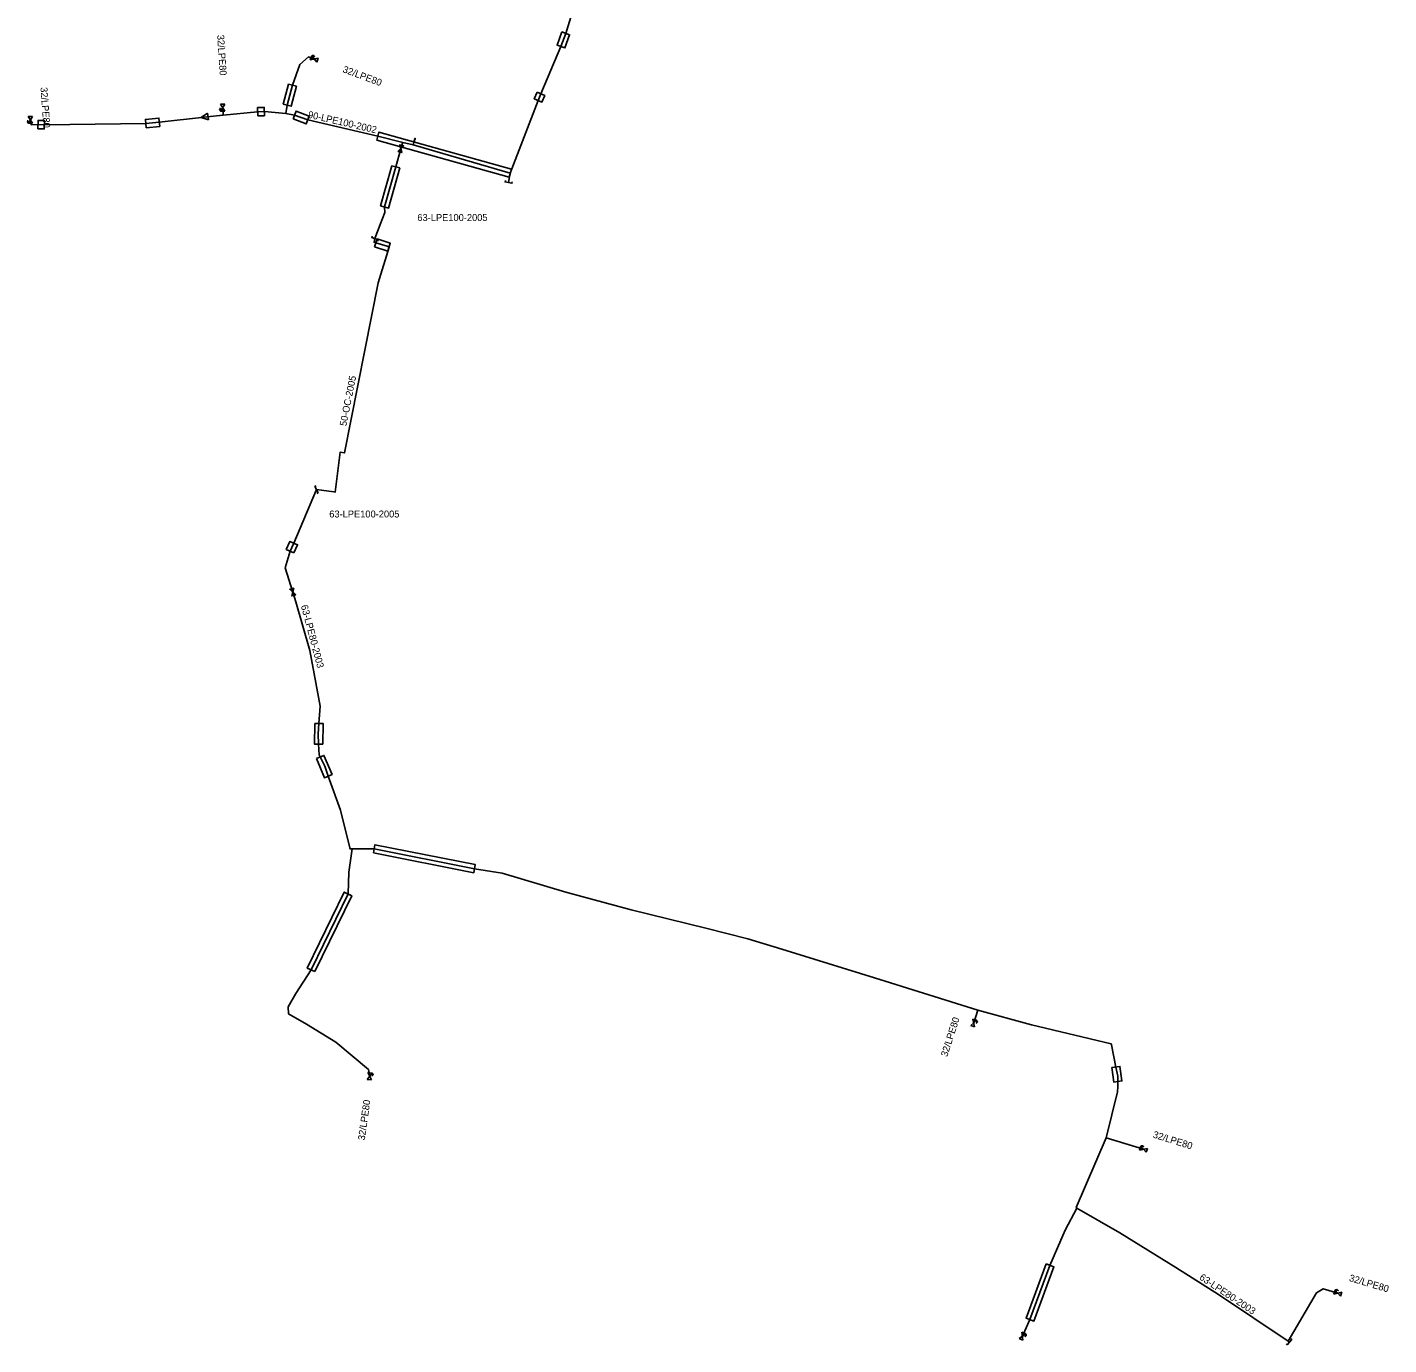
# Model space of a CAD drawing. Extents: x -787723 to -786204, y -1153846 to -1152384.
# Drawn here: x -787467.5 to -787271.2, y -1153161.4 to -1152971.6 of the extents above; entities that cross this region are included whole.
import ezdxf

# ---------------------------------------------------------------- set-up
doc = ezdxf.new("R2010")
doc.units = 0
for name, color, linetype in [('Vrstva 1', 7, 'Continuous'), ('Vrstva 21', 7, 'Continuous'), ('Vrstva 22', 7, 'Continuous'), ('Vrstva 25', 7, 'Continuous'), ('Vrstva 26', 7, 'Continuous'), ('Vrstva 28', 7, 'Continuous'), ('Vrstva 29', 7, 'Continuous'), ('Vrstva 31', 7, 'Continuous'), ('Vrstva 32', 7, 'Continuous')]:
    doc.layers.add(name, color=color, linetype=linetype)

# ---------------------------------------------------------------- blocks, each defined once
blk = doc.blocks.new('DEC123')
at = {"layer": 'Vrstva 1'}
blk.add_lwpolyline([(0.2, 0.5), (0, 0.5), (0, -0.5), (-0.2, -0.5)], dxfattribs=at)
blk = doc.blocks.new('DEC122')
at = {"layer": 'Vrstva 1'}
for p, q in [((-0.5, 0.5), (0.5, 0)), ((-0.5, -0.5), (-0.5, 0.5)), ((0.5, 0), (-0.5, -0.5))]:
    blk.add_line(p, q, dxfattribs=at)
blk = doc.blocks.new('DEC063-SN')
at = {"layer": 'Vrstva 1'}
for p, q in [((-0.5, -0.3), (0.5, 0.3)), ((0.5, -0.3), (-0.5, 0.3)), ((-0.5, 0.3), (-0.5, -0.3)), ((0.5, 0.3), (0.5, -0.3)), ((0.126, -0.318), (0.126, -0.458)), ((0.126, -0.384), (0.206, -0.384)), ((0.206, -0.458), (0.206, -0.318)), ((0.366, -0.458), (0.366, -0.318))]:
    blk.add_line(p, q, dxfattribs=at)
for points in [[(0.246, -0.318), (0.246, -0.418), (0.252, -0.438), (0.264, -0.451), (0.281, -0.458), (0.292, -0.458), (0.309, -0.451), (0.321, -0.438), (0.326, -0.418), (0.326, -0.318)], [(0.366, -0.318), (0.418, -0.318), (0.435, -0.325), (0.441, -0.331), (0.446, -0.344), (0.446, -0.364), (0.441, -0.378), (0.435, -0.384), (0.418, -0.391), (0.366, -0.391)]]:
    blk.add_lwpolyline(points, dxfattribs=at)
blk = doc.blocks.new('DEC130')
at = {"layer": 'Vrstva 1'}
blk.add_lwpolyline([(0.2, 0.5), (0, 0.5), (0, -0.5), (0.2, -0.5)], dxfattribs=at)
blk = doc.blocks.new('DEC124')
at = {"layer": 'Vrstva 1'}
blk.add_lwpolyline([(-0.5, 0.3), (0.5, -0.3), (0.5, 0.3), (-0.5, -0.3), (-0.5, 0.3)], dxfattribs=at)
blk = doc.blocks.new('DEC127')
at = {"layer": 'Vrstva 1'}
for p, q in [((0, 0.56), (0, 0.99)), ((0, 0.42), (0, -0.01))]:
    blk.add_line(p, q, dxfattribs=at)
blk.add_lwpolyline([(-0.07, 0.82), (0, 0.99), (0.07, 0.82)], dxfattribs=at)
blk.add_circle((0, 0.49), 0.07, dxfattribs=at)

msp = doc.modelspace()

# ---------------------------------------------------------------- linework, layer by layer
at = {"layer": 'Vrstva 21'}
for points in [[(-787334.68, -1152764.41), (-787335.37, -1152773.31), (-787335.76, -1152787.99), (-787335.85, -1152796.93), (-787336.15, -1152812.79), (-787336.74, -1152825.56), (-787338.63, -1152836.89), (-787341.8, -1152849.26), (-787345.88, -1152859.17), (-787354.3, -1152875.54), (-787363.3, -1152892.46), (-787369.92, -1152905.89), (-787373.75, -1152916.59), (-787378.4, -1152930.29), (-787381.12, -1152940.81), (-787381.21, -1152941.76), (-787383.36, -1152950.95), (-787386.31, -1152960.92), (-787389.85, -1152972.44), (-787390.54, -1152974.33), (-787393.42, -1152981.16), (-787393.84, -1152982.11), (-787397.85, -1152992.58)], [(-787413.33, -1152988.15), (-787416.93, -1152987.25), (-787427.03, -1152984.92), (-787428.92, -1152984.21), (-787430.18, -1152984.01), (-787433.28, -1152983.72), (-787434.25, -1152983.74), (-787439.24, -1152984.24), (-787441.56, -1152984.45), (-787441.9, -1152984.5)], [(-787413.33, -1152988.15), (-787413.51, -1152988.66), (-787413.62, -1152989.06)], [(-787397.85, -1152992.58), (-787411.83, -1152988.52), (-787413.33, -1152988.15)], [(-787413.62, -1152989.06), (-787414.35, -1152991.67), (-787415.96, -1152997.45), (-787415.94, -1152998.26)], [(-787397.85, -1152992.58), (-787398.1, -1152993.95)], [(-787415.94, -1152998.26), (-787416.59, -1153000), (-787417.34, -1153002.02)], [(-787417.34, -1153002.02), (-787417.48, -1153002.53), (-787417.21, -1153002.64), (-787415.57, -1153003.11), (-787415.32, -1153003.25), (-787416.86, -1153008.38), (-787421.72, -1153032.9), (-787422.38, -1153032.81), (-787423.06, -1153038.53), (-787423.27, -1153038.5), (-787425.77, -1153038.19)], [(-787430.26, -1153049.44), (-787429.57, -1153047.05), (-787429.34, -1153046.53), (-787429.05, -1153045.89), (-787425.77, -1153038.19)], [(-787430.26, -1153049.44), (-787429.19, -1153052.94)], [(-787429.19, -1153052.94), (-787428.77, -1153054.34), (-787426.73, -1153061.36), (-787425.26, -1153069.4), (-787425.43, -1153071.87), (-787425.53, -1153073.37), (-787425.46, -1153074.86), (-787425.39, -1153076.42), (-787425.24, -1153076.71), (-787424.57, -1153078.05), (-787424.07, -1153079.46), (-787422.33, -1153084.37), (-787420.96, -1153089.78)], [(-787420.96, -1153089.78), (-787420.92, -1153089.96), (-787420.62, -1153089.96), (-787417.46, -1153089.95), (-787402.99, -1153092.81), (-787399.02, -1153093.46), (-787389.85, -1153096.19), (-787380.41, -1153098.73), (-787369.68, -1153101.37), (-787363.63, -1153102.9), (-787358.73, -1153104.42), (-787345.38, -1153108.54), (-787330.47, -1153113.21), (-787322.74, -1153115.32), (-787311.24, -1153118.07), (-787311.22, -1153118.17)], [(-787311.22, -1153118.17), (-787310.58, -1153121.4), (-787310.31, -1153122.72), (-787310.29, -1153123.48), (-787310.27, -1153124.18), (-787310.36, -1153124.94), (-787311.95, -1153131.57), (-787316.28, -1153141.64), (-787316.2, -1153141.75), (-787310, -1153145.29), (-787301.94, -1153150.29), (-787295.79, -1153154.17), (-787285.74, -1153160.87), (-787285.56, -1153161.04)]]:
    msp.add_lwpolyline(points, dxfattribs=at)
at = {"layer": 'Vrstva 29'}
for points in [[(-787390.41, -1152972.23), (-787389.29, -1152972.65), (-787389.98, -1152974.53), (-787391.1, -1152974.12)], [(-787429.81, -1152979.76), (-787428.65, -1152980.06), (-787429.4, -1152982.94), (-787430.56, -1152982.64)], [(-787393.97, -1152980.92), (-787392.87, -1152981.4), (-787393.29, -1152982.35), (-787394.39, -1152981.87)], [(-787450.31, -1152986.03), (-787450.43, -1152984.83), (-787448.48, -1152984.64), (-787448.36, -1152985.84)], [(-787434.24, -1152984.34), (-787434.26, -1152983.14), (-787433.29, -1152983.12), (-787433.27, -1152984.32)], [(-787429.13, -1152984.77), (-787428.71, -1152983.65), (-787426.82, -1152984.36), (-787427.24, -1152985.48)], [(-787465.94, -1152986.18), (-787465.88, -1152984.98), (-787464.95, -1152985.02), (-787465.01, -1152986.22)], [(-787417.09, -1152987.83), (-787416.77, -1152986.67), (-787397.69, -1152992), (-787398.01, -1152993.16)], [(-787414.93, -1152991.51), (-787413.77, -1152991.83), (-787415.39, -1152997.61), (-787416.54, -1152997.29)], [(-787417.39, -1153003.21), (-787417.03, -1153002.07), (-787415.14, -1153002.68), (-787415.5, -1153003.82)], [(-787429.02, -1153047.29), (-787430.12, -1153046.8), (-787429.6, -1153045.64), (-787428.5, -1153046.14)], [(-787426.03, -1153071.87), (-787424.83, -1153071.88), (-787424.86, -1153074.86), (-787426.06, -1153074.85)], [(-787425.79, -1153076.95), (-787424.69, -1153076.48), (-787423.52, -1153079.23), (-787424.62, -1153079.7)], [(-787417.57, -1153090.54), (-787417.34, -1153089.36), (-787402.88, -1153092.22), (-787403.11, -1153093.4)], [(-787426.02, -1153107.64), (-787427.1, -1153107.12), (-787421.76, -1153096.19), (-787420.68, -1153096.71)], [(-787311.17, -1153121.48), (-787309.98, -1153121.31), (-787309.7, -1153123.4), (-787310.89, -1153123.56)], [(-787320.63, -1153149.77), (-787319.5, -1153150.18), (-787322.39, -1153157.99), (-787323.52, -1153157.57)]]:
    msp.add_lwpolyline(points, close=True, dxfattribs=at)
at = {"layer": 'Vrstva 31'}
for points in [[(-787430.18, -1152984.01), (-787429.98, -1152982.79), (-787429.23, -1152979.91), (-787428.18, -1152976.94), (-787426.92, -1152975.83), (-787426.09, -1152976.14)], [(-787441.9, -1152984.5), (-787448.42, -1152985.24), (-787450.37, -1152985.43), (-787464.98, -1152985.62), (-787465.91, -1152985.58), (-787466.9, -1152985.6), (-787466.99, -1152984.9)], [(-787439.24, -1152984.24), (-787439.28, -1152983.15)], [(-787420.62, -1153089.96), (-787421.1, -1153093.3), (-787421.22, -1153096.45), (-787426.56, -1153107.38), (-787428.77, -1153110.77), (-787429.87, -1153112.71), (-787429.78, -1153113.74), (-787427.19, -1153115.21), (-787423, -1153117.82), (-787418.26, -1153121.76), (-787418.1, -1153122.72)], [(-787330.47, -1153113.21), (-787331.06, -1153115.04)], [(-787311.95, -1153131.57), (-787306.6, -1153133.24)], [(-787316.2, -1153141.75), (-787317.88, -1153144.92), (-787320.07, -1153149.97), (-787322.96, -1153157.78), (-787324.04, -1153160.16)], [(-787285.74, -1153160.87), (-787281.64, -1153153.94), (-787280.7, -1153153.34), (-787278.58, -1153153.97)]]:
    msp.add_lwpolyline(points, dxfattribs=at)

# ---------------------------------------------------------------- block references
at = {"layer": 'Vrstva 22'}
for name, p, rotation in [('DEC124', (-787413.62, -1152989.06), 74.49066386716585), ('DEC130', (-787398.1, -1152993.95), 78.80488889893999), ('DEC124', (-787429.19, -1153052.94), -72.98588883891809), ('DEC130', (-787285.56, -1153161.04), 137.26475556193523)]:
    msp.add_blockref(name, p, dxfattribs=dict(at, rotation=rotation))
at = {"layer": 'Vrstva 25'}
for p, rotation in [((-787417.34, -1153002.02), 69.57766670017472), ((-787425.77, -1153038.19), 28.653794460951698)]:
    msp.add_blockref('DEC123', p, dxfattribs=dict(at, rotation=rotation))
at = {"layer": 'Vrstva 26', "rotation": -171.63411382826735}
msp.add_blockref('DEC122', (-787441.9, -1152984.5), dxfattribs=at)
at = {"layer": 'Vrstva 28', "rotation": -15.302933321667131}
msp.add_blockref('DEC127', (-787411.83, -1152988.52), dxfattribs=at)
at = {"layer": 'Vrstva 32'}
for p, rotation in [((-787426.09, -1152976.14), 159.6342277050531), ((-787439.28, -1152983.15), -89.8477805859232), ((-787466.99, -1152984.9), -89.4108611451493), ((-787331.06, -1153115.04), 72.22251389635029), ((-787418.1, -1153122.72), 84.16278058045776), ((-787306.6, -1153133.24), 162.1147944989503), ((-787278.58, -1153153.97), 162.466555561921), ((-787324.04, -1153160.16), 65.5052166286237)]:
    msp.add_blockref('DEC063-SN', p, dxfattribs=dict(at, rotation=rotation))

# ---------------------------------------------------------------- texts
at = {"layer": 'Vrstva 21'}
for s, rotation, p in [('90-LPE100-2002', 347.01, (-787427.07, -1152984.58)), ('50-OC-2005', 78.789, (-787421.47, -1153029.09)), ('63-LPE80-2003', 284.791, (-787428.02, -1153054.93)), ('63-LPE80-2003', 326.293, (-787298.64, -1153151.92))]:
    msp.add_text(s, height=1, rotation=rotation, dxfattribs=at).set_placement(p)
for p in [(-787411.23, -1152999.48), (-787423.93, -1153042.2)]:
    msp.add_text('63-LPE100-2005', height=1, dxfattribs=at).set_placement(p)
at = {"layer": 'Vrstva 31'}
for rotation, p in [(273.737, (-787440.08, -1152972.68)), (339.533, (-787422.08, -1152978.01)), (274.206, (-787465.55, -1152980.23)), (72.223, (-787334.88, -1153119.99)), (81.953, (-787418.82, -1153132)), (342.68, (-787305.32, -1153131.53)), (343.425, (-787277.04, -1153152.2))]:
    msp.add_text('32/LPE80', height=1, rotation=rotation, dxfattribs=at).set_placement(p)

doc.saveas('drawing.dxf')
